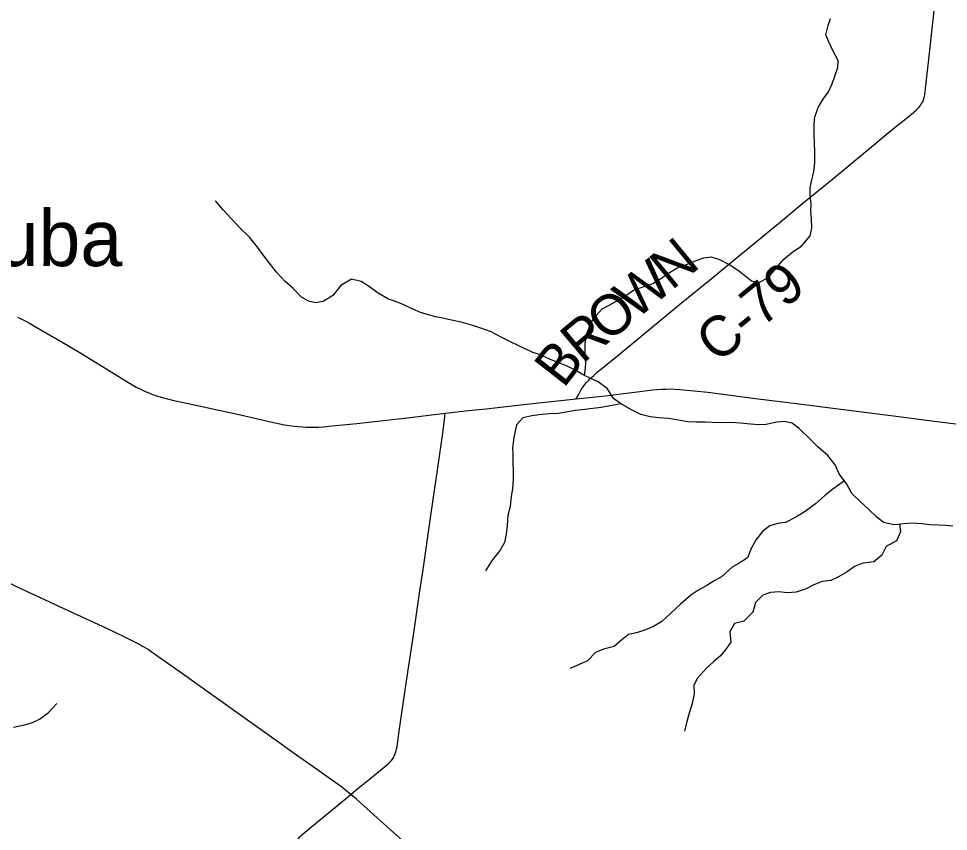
# Model space of a CAD drawing. Extents: x 0 to 34, y 0 to 22.
# Drawn here: x 5.838 to 7.143, y 16.226 to 17.368 of the extents above; entities that cross this region are included whole.
import ezdxf

# ---------------------------------------------------------------- set-up
doc = ezdxf.new("R2010")
doc.units = 0
for name, color, linetype in [('GM_X_County_Road', 7, 'Continuous'), ('GM_X_County_Road_Text', 7, 'Continuous'), ('GM_X_Minor_River', 7, 'Continuous'), ('GM_X_State_Route', 7, 'Continuous'), ('GM_X_Unincorporated_Text', 7, 'Continuous')]:
    doc.layers.add(name, color=color, linetype=linetype)

msp = doc.modelspace()

# ---------------------------------------------------------------- linework, layer by layer
at = {"layer": 'GM_X_County_Road'}
for points in [[(6.6206, 16.8334), (6.624, 16.8393), (6.6279, 16.8464), (6.6297, 16.849), (6.6315, 16.8516), (6.6333, 16.8539), (6.635, 16.856), (6.6365, 16.8577), (6.6384, 16.8597), (6.6405, 16.8619), (6.6424, 16.8637), (6.6455, 16.8664), (6.6499, 16.8703), (6.6787, 16.8939), (6.7117, 16.9213), (6.7659, 16.9659), (6.8102, 17.0021), (6.8427, 17.029), (6.9048, 17.0797), (6.9191, 17.0916), (6.9276, 17.0989), (6.9392, 17.1084), (6.9805, 17.1422), (7.0053, 17.1629), (7.0409, 17.192), (7.0595, 17.2075), (7.0909, 17.233), (7.0984, 17.2394), (7.1018, 17.2429), (7.1041, 17.2457), (7.1058, 17.2482), (7.1073, 17.2508), (7.1084, 17.2536), (7.1094, 17.257), (7.1102, 17.2607), (7.1108, 17.265), (7.1114, 17.2693), (7.1123, 17.2773), (7.1161, 17.3107), (7.1322, 17.4601)], [(6.3043, 16.2778), (6.312, 16.2842), (6.3352, 16.3029), (6.354, 16.3182), (6.3567, 16.3207), (6.3591, 16.3229), (6.361, 16.3251), (6.3628, 16.3273), (6.3642, 16.3298), (6.3654, 16.3317), (6.3664, 16.334), (6.3672, 16.3363), (6.368, 16.3388), (6.3686, 16.3418), (6.3693, 16.345), (6.3698, 16.3488), (6.3725, 16.3666), (6.3784, 16.4084), (6.3845, 16.4496), (6.3873, 16.468), (6.3929, 16.5048), (6.4015, 16.5638), (6.4049, 16.5872), (6.4167, 16.6696), (6.4266, 16.7366), (6.4336, 16.7852), (6.4359, 16.8043), (6.437, 16.8133)], [(6.3043, 16.2778), (6.2999, 16.2815), (6.2911, 16.2884), (6.2786, 16.2975), (6.2481, 16.3189), (6.2313, 16.3308), (6.1904, 16.3601), (6.0977, 16.4259), (6.0795, 16.439), (6.0568, 16.4552), (6.029, 16.475), (6.0243, 16.4782), (6.0197, 16.4812), (6.0134, 16.4851), (6.0096, 16.4872), (6.0058, 16.4893), (6.0001, 16.4921), (5.9947, 16.4948), (5.9679, 16.5079), (5.8969, 16.5408), (5.8756, 16.5509), (5.8446, 16.5652), (5.8199, 16.577)], [(6.2145, 16.0932), (6.2186, 16.1478), (6.2214, 16.1825), (6.2222, 16.1911), (6.2229, 16.1966), (6.2236, 16.2003), (6.2245, 16.2037), (6.2257, 16.2071), (6.227, 16.2099), (6.2283, 16.212), (6.2299, 16.2145), (6.2314, 16.2164), (6.2332, 16.2185), (6.2356, 16.2209), (6.2406, 16.2254), (6.2521, 16.2348), (6.2574, 16.2391), (6.2781, 16.256), (6.3043, 16.2778)], [(6.3779, 16.2123), (6.3368, 16.2492), (6.3122, 16.2711), (6.3043, 16.2778)]]:
    msp.add_lwpolyline(points, dxfattribs=at)
at = {"layer": 'GM_X_Minor_River'}
for points in [[(6.6327, 16.8664), (6.6336, 16.873), (6.6345, 16.8829), (6.6332, 16.8969), (6.6334, 16.9106), (6.6354, 16.9238), (6.6398, 16.9355), (6.6448, 16.9457), (6.6572, 16.96), (6.6671, 16.9652), (6.6782, 16.9711), (6.689, 16.9778), (6.7012, 16.986), (6.7134, 16.9904), (6.7283, 16.9955), (6.7398, 17.0026), (6.7517, 17.0108), (6.7624, 17.0175), (6.7769, 17.0226), (6.7891, 17.0278), (6.8002, 17.0318), (6.8101, 17.0328), (6.8218, 17.0292), (6.8373, 17.0211), (6.8505, 17.0125), (6.867, 16.9994), (6.8768, 16.9966), (6.8902, 17.004), (6.9018, 17.0172), (6.9122, 17.0296), (6.9253, 17.0404), (6.9372, 17.0482), (6.9495, 17.0625), (6.9519, 17.0731), (6.951, 17.0868), (6.9504, 17.0974), (6.9509, 17.1073), (6.9492, 17.1198), (6.9493, 17.1297), (6.9513, 17.1395), (6.9545, 17.1524), (6.9558, 17.1649), (6.9561, 17.1812), (6.9554, 17.1915), (6.9549, 17.2052), (6.9551, 17.22), (6.956, 17.2298), (6.9607, 17.243), (6.9677, 17.2547), (6.975, 17.2649), (6.9801, 17.2758), (6.9841, 17.2868), (6.9884, 17.2992), (6.9885, 17.3087), (6.9822, 17.321), (6.9756, 17.3351), (6.9712, 17.345), (6.9744, 17.3579), (6.9779, 17.3677)], [(6.3053, 17.0018), (6.2903, 16.9928), (6.2791, 16.9789), (6.2657, 16.9704), (6.2551, 16.9686), (6.2448, 16.9706), (6.235, 16.9761), (6.2231, 16.9888), (6.2122, 16.9984), (6.2002, 17.0115), (6.1901, 17.0241), (6.1823, 17.0345), (6.1733, 17.0464), (6.1621, 17.0605), (6.1482, 17.074), (6.1366, 17.0867), (6.1254, 17.099), (6.1142, 17.1117)], [(7.1495, 16.6545), (7.1393, 16.6554), (7.1294, 16.6559), (7.1173, 16.6564), (7.1059, 16.6577), (7.0926, 16.6587), (7.0812, 16.658), (7.0675, 16.6567), (7.0523, 16.6599), (7.0426, 16.6677), (7.0317, 16.678), (7.0201, 16.6888), (7.0077, 16.7007), (7.0006, 16.7134), (6.9902, 16.7283), (6.9843, 16.7409), (6.9739, 16.754), (6.9603, 16.7659), (6.9491, 16.777), (6.9341, 16.7917), (6.9239, 16.7994), (6.9133, 16.8018), (6.9019, 16.8008), (6.8875, 16.7976), (6.8776, 16.797), (6.8654, 16.7979), (6.8514, 16.7992), (6.8381, 16.8001), (6.8263, 16.7999), (6.8119, 16.8001), (6.802, 16.8006), (6.7891, 16.8008), (6.777, 16.8013), (6.7618, 16.8038), (6.7505, 16.8058), (6.7368, 16.8067), (6.7247, 16.8084), (6.7114, 16.8116), (6.6986, 16.8179), (6.6846, 16.826), (6.6733, 16.8341), (6.6648, 16.8475), (6.6516, 16.8572), (6.6414, 16.8619), (6.6316, 16.8669), (6.6203, 16.8735), (6.6071, 16.8798), (6.5928, 16.8857), (6.5826, 16.8896), (6.5705, 16.8951), (6.5599, 16.8986), (6.5403, 16.908), (6.5286, 16.9138), (6.5157, 16.9201), (6.5014, 16.9275), (6.4855, 16.9334), (6.4757, 16.9365), (6.4594, 16.9413), (6.4458, 16.9441), (6.4356, 16.9465), (6.4238, 16.9486), (6.4136, 16.9514), (6.4023, 16.9549), (6.3913, 16.9596), (6.3777, 16.9659), (6.3671, 16.9702), (6.3573, 16.9737), (6.3426, 16.9819), (6.3291, 16.992), (6.3189, 16.9982), (6.3053, 17.0018)], [(6.6841, 16.8264), (6.6683, 16.8236), (6.6561, 16.8215), (6.6443, 16.8201), (6.6329, 16.8183), (6.6192, 16.817), (6.6066, 16.8149), (6.596, 16.8127), (6.5827, 16.8125), (6.569, 16.8108), (6.5587, 16.8098), (6.5461, 16.8066), (6.5369, 16.7968), (6.5332, 16.779), (6.5315, 16.7646), (6.5317, 16.7551), (6.532, 16.7452), (6.5322, 16.7312), (6.5324, 16.7206), (6.5315, 16.7069), (6.5294, 16.6967), (6.5281, 16.6823), (6.5249, 16.6694), (6.5239, 16.6558), (6.5226, 16.6433), (6.5202, 16.6315), (6.514, 16.621), (6.5028, 16.6067), (6.4935, 16.592)], [(6.9973, 16.7181), (6.9812, 16.7064), (6.9693, 16.6974), (6.9566, 16.6862), (6.9424, 16.6754), (6.9294, 16.6672), (6.9145, 16.6598), (6.9038, 16.6584), (6.8928, 16.6552), (6.8828, 16.6477), (6.8735, 16.6361), (6.8665, 16.6232), (6.8614, 16.61), (6.8495, 16.6026), (6.8399, 16.597), (6.8249, 16.5835), (6.8154, 16.5783), (6.8058, 16.5724), (6.7916, 16.5642), (6.7817, 16.5575), (6.7671, 16.5452), (6.7532, 16.5321), (6.7413, 16.5208), (6.7294, 16.5138), (6.7183, 16.509), (6.7054, 16.505), (6.6943, 16.5025), (6.6847, 16.495), (6.674, 16.4857), (6.6591, 16.4817), (6.648, 16.4773), (6.6369, 16.4656), (6.6258, 16.4608), (6.6124, 16.4546)], [(7.0748, 16.6574), (7.0761, 16.6467), (7.0706, 16.6339), (7.0561, 16.6261), (7.0498, 16.614), (7.0387, 16.6043), (7.0235, 16.6026), (7.0116, 16.5982), (7.0013, 16.5907), (6.989, 16.5833), (6.9783, 16.5785), (6.9661, 16.5768), (6.9547, 16.5724), (6.9436, 16.5664), (6.9295, 16.5621), (6.9173, 16.5611), (6.9052, 16.5624), (6.8938, 16.5614), (6.8831, 16.5577), (6.8727, 16.5476), (6.8687, 16.534), (6.856, 16.5213), (6.843, 16.518), (6.8364, 16.5063), (6.8378, 16.4919), (6.8316, 16.4821), (6.8234, 16.4723), (6.8138, 16.4641), (6.8038, 16.4551), (6.7911, 16.4412), (6.786, 16.4314), (6.7863, 16.4193), (6.7838, 16.4053), (6.7794, 16.3921), (6.7762, 16.3803), (6.773, 16.3667)], [(5.8307, 16.3724), (5.8464, 16.3757), (5.8574, 16.3789), (5.8674, 16.3837), (5.8796, 16.3923), (5.8916, 16.4054)]]:
    msp.add_lwpolyline(points, dxfattribs=at)
at = {"layer": 'GM_X_State_Route'}
msp.add_lwpolyline([(5.8364, 16.9483), (5.8407, 16.9463), (5.8451, 16.9441), (5.849, 16.9421), (5.8532, 16.9397), (5.8603, 16.9357), (5.9081, 16.9079), (5.9278, 16.8961), (5.9897, 16.8579), (6.0032, 16.8501), (6.0096, 16.8469), (6.0149, 16.8443), (6.0208, 16.8418), (6.0259, 16.8397), (6.0294, 16.8385), (6.0329, 16.8373), (6.0369, 16.8361), (6.0413, 16.8348), (6.0469, 16.8334), (6.054, 16.8316), (6.0759, 16.8271), (6.1494, 16.8111), (6.1918, 16.8014), (6.2113, 16.7972), (6.2248, 16.795), (6.2306, 16.7945), (6.2367, 16.794), (6.2414, 16.7938), (6.2473, 16.7936), (6.2529, 16.7937), (6.2591, 16.7938), (6.266, 16.7943), (6.2734, 16.7949), (6.313, 16.799), (6.3834, 16.8069), (6.437, 16.8133), (6.4414, 16.8138), (6.4698, 16.817), (6.4945, 16.8195), (6.547, 16.8254), (6.6206, 16.8334), (6.6619, 16.8379), (6.6989, 16.8425), (6.7284, 16.8463), (6.7342, 16.8467), (6.7408, 16.8473), (6.7466, 16.8473), (6.7531, 16.8474), (6.7593, 16.847), (6.7661, 16.8467), (6.7865, 16.8449), (6.8056, 16.8428), (6.8728, 16.8342), (6.9338, 16.8265), (6.9887, 16.8193), (7.0664, 16.8097), (7.1163, 16.8033), (7.1909, 16.7939)], dxfattribs=at)

# ---------------------------------------------------------------- texts
at = {"layer": 'GM_X_County_Road_Text'}
for s, height, rotation, p in [('N', 0.0568, 39.4155, (6.7547, 16.985)), ('W', 0.0568, 39.4117, (6.7039, 16.9432)), ('C-79', 0.05682, 39.4103, (6.8192, 16.8819)), ('O', 0.0568, 39.417, (6.6652, 16.9114)), ('R', 0.0568, 39.8046, (6.6295, 16.8816)), ('B', 0.0568, 52.0832, (6.603, 16.8471))]:
    msp.add_text(s, height=height, rotation=rotation, dxfattribs=at).set_placement(p)
at = {"layer": 'GM_X_Unincorporated_Text'}
msp.add_text('Cuba', height=0.07898, rotation=0, dxfattribs=at).set_placement((5.7309, 17.0199))

doc.saveas('drawing.dxf')
